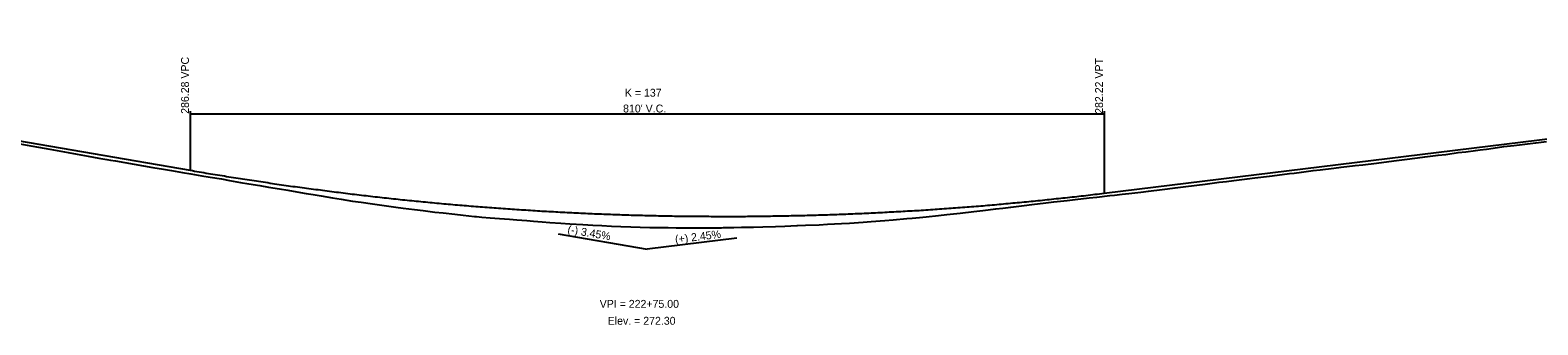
# Model space of a CAD drawing. Extents: x 1876258 to 1926563, y 729739 to 834437.
# Drawn here: x 1900091 to 1901427, y 828757 to 829018 of the extents above; entities that cross this region are included whole.
import ezdxf

# ---------------------------------------------------------------- set-up
doc = ezdxf.new("R2010")
doc.units = 0
for name, color, linetype in [('RD_EX_BldgApp', 7, 'Continuous'), ('RD_EX_H2O_BlueLn', 7, 'Continuous'), ('RD_EX_RailRoad', 7, 'Continuous'), ('RD_HC_Data', 7, 'Continuous'), ('RD_HC_TX_Sta50', 7, 'Continuous'), ('RD_PD_ALT5_CL', 7, 'Continuous')]:
    doc.layers.add(name, color=color, linetype=linetype)

msp = doc.modelspace()

# ---------------------------------------------------------------- linework, layer by layer
at = {"layer": 'RD_EX_BldgApp'}
for points in [[(1900704.1, 828843.2), (1900705.7, 828843.4), (1900711.3, 828843.5), (1900714.9, 828843.6), (1900721.8, 828843.7), (1900732.4, 828843.9), (1900740.7, 828844.2), (1900752, 828844.5), (1900760.1, 828844.7), (1900770.9, 828845.1), (1900771.3, 828845.1), (1900778.6, 828845.4), (1900790.6, 828845.9), (1900798, 828846.3), (1900810.5, 828847), (1900817.6, 828847.4), (1900829.7, 828848.2), (1900836.7, 828848.8), (1900848.8, 828849.6), (1900856.2, 828850.2), (1900868.3, 828851.4), (1900873, 828851.7), (1900879.6, 828852.3), (1900885.5, 828853), (1900896.3, 828854.2), (1900903.6, 828855), (1900915.4, 828856.3), (1900927.7, 828857.7), (1900935.5, 828858.5), (1900947, 828860), (1900953.4, 828860.7), (1900960.5, 828861.6), (1900972.2, 828863), (1900979.1, 828863.8), (1900991.5, 828865.2), (1900998.5, 828866.1), (1901010.3, 828867.4), (1901017.4, 828868.2), (1901029.7, 828869.7), (1901036.5, 828870.4), (1901048.3, 828871.8), (1901052.2, 828872.2), (1901059, 828873), (1901065, 828873.6), (1901075.5, 828874.9), (1901082.5, 828875.8), (1901094.4, 828877.2), (1901106.1, 828878.7), (1901113.1, 828879.5), (1901125.4, 828881), (1901132.7, 828881.9), (1901144.9, 828883.5), (1901151.5, 828884.3), (1901158, 828885.1), (1901169.9, 828886.6), (1901176.6, 828887.4), (1901189.7, 828889.1), (1901196.3, 828889.9), (1901207.4, 828891.2), (1901211.4, 828891.7), (1901218.1, 828892.6), (1901228.2, 828893.9), (1901234.6, 828894.6), (1901246.8, 828896.1), (1901253.1, 828896.9), (1901265.5, 828898.3), (1901272.3, 828899.1), (1901284.4, 828900.6), (1901290.9, 828901.4), (1901302.2, 828902.8), (1901309.2, 828903.6), (1901320.9, 828905.1), (1901327.3, 828906), (1901339, 828907.5), (1901345.9, 828908.3), (1901356.9, 828909.8), (1901363.5, 828910.6), (1901372.1, 828911.7), (1901376.3, 828912.2), (1901382, 828913), (1901391.7, 828914.4), (1901397.2, 828915.1), (1901406.1, 828916.2), (1901411.3, 828916.8), (1901420.5, 828917.9), (1901425.8, 828918.6), (1901435, 828919.7)], [(1900082.1, 828917.5), (1900092.1, 828915.8), (1900098.7, 828914.6), (1900108.7, 828912.8), (1900115.4, 828911.6), (1900125.2, 828909.9), (1900133.1, 828908.4), (1900142.8, 828906.6), (1900152.1, 828905), (1900159.3, 828903.8), (1900162.5, 828903.2), (1900166.9, 828902.4), (1900183.4, 828899.6), (1900200, 828896.7), (1900209.4, 828895.2), (1900216.6, 828894), (1900226.5, 828892.3), (1900233.8, 828891), (1900243.6, 828889.4), (1900250.9, 828888.2), (1900260.8, 828886.5), (1900268.1, 828885.2), (1900277.9, 828883.4), (1900285.3, 828882.3), (1900295, 828880.6), (1900302.5, 828879.3), (1900312.2, 828877.7), (1900319.6, 828876.5), (1900330.9, 828874.5), (1900336, 828873.7), (1900342.1, 828872.6), (1900349.3, 828871.4), (1900359.3, 828869.7), (1900366.9, 828868.5), (1900377.1, 828866.9), (1900384.6, 828865.8), (1900394.8, 828864.4), (1900405.1, 828863), (1900415.3, 828861.5), (1900422, 828860.6), (1900432.1, 828859.3), (1900439.6, 828858.4), (1900449.9, 828857.2), (1900457.3, 828856.4), (1900467.6, 828855.2), (1900475.1, 828854.4), (1900485.2, 828853.3), (1900486.8, 828853.2), (1900491.7, 828852.7), (1900499.1, 828852.1), (1900507.3, 828851.4), (1900516.2, 828850.8), (1900522.8, 828850.2), (1900531.5, 828849.6), (1900537.3, 828849.1), (1900545, 828848.4), (1900551.8, 828847.9), (1900561.6, 828847.2), (1900569.7, 828846.7), (1900581, 828846), (1900589.9, 828845.6), (1900597.9, 828845.1), (1900606.6, 828844.7), (1900614.9, 828844.4), (1900623.8, 828844), (1900631.9, 828843.7), (1900640.6, 828843.6), (1900647.5, 828843.6), (1900656.7, 828843.4), (1900663.9, 828843.3), (1900672.6, 828843.3), (1900680.5, 828843.3), (1900689.5, 828843.3), (1900695.2, 828843.1), (1900704.1, 828843.2)]]:
    msp.add_lwpolyline(points, dxfattribs=at)
at = {"layer": 'RD_EX_H2O_BlueLn'}
for p, q in [((1900233.1, 828946.7), (1900233.1, 828894.2)), ((1901043.1, 828946.7), (1901043.1, 828873.9)), ((1900233.1, 828944.2), (1901043.1, 828944.2))]:
    msp.add_line(p, q, dxfattribs=at)
at = {"layer": 'RD_HC_TX_Sta50'}
for p in [(1900559.2, 828837.9), (1900717.5, 828834)]:
    msp.add_line(p, (1900638.1, 828824.3), dxfattribs=at)
at = {"layer": 'RD_PD_ALT5_CL'}
for p, q in [((1901043.1, 828873.9), (1902223.1, 829018.3)), ((1900043.1, 828927), (1900233.1, 828894.2))]:
    msp.add_line(p, q, dxfattribs=at)
msp.add_spline([(1900233.1, 828894.2), (1900249.3, 828891.4), (1900265.5, 828888.8), (1900281.7, 828886.2), (1900297.9, 828883.8), (1900314.1, 828881.4), (1900330.3, 828879.1), (1900346.5, 828877), (1900362.7, 828874.9), (1900378.9, 828872.9), (1900395.1, 828871), (1900411.3, 828869.2), (1900427.5, 828867.5), (1900443.7, 828865.9), (1900459.9, 828864.4), (1900476.1, 828863), (1900492.3, 828861.7), (1900508.5, 828860.5), (1900524.7, 828859.4), (1900540.9, 828858.3), (1900557.1, 828857.4), (1900573.3, 828856.6), (1900589.5, 828855.8), (1900605.7, 828855.2), (1900621.9, 828854.6), (1900638.1, 828854.2), (1900654.3, 828853.8), (1900670.5, 828853.5), (1900686.7, 828853.4), (1900702.9, 828853.3), (1900719.1, 828853.3), (1900735.3, 828853.5), (1900751.5, 828853.7), (1900767.7, 828854), (1900783.9, 828854.4), (1900800.1, 828854.9), (1900816.3, 828855.5), (1900832.5, 828856.2), (1900848.7, 828857), (1900864.9, 828857.9), (1900881.1, 828858.8), (1900897.3, 828859.9), (1900913.5, 828861.1), (1900929.7, 828862.3), (1900945.9, 828863.7), (1900962.1, 828865.2), (1900978.3, 828866.7), (1900994.5, 828868.4), (1901010.7, 828870.1), (1901026.9, 828871.9), (1901043.1, 828873.9)], degree=3, dxfattribs=at)

# ---------------------------------------------------------------- texts
at = {"layer": 'RD_EX_H2O_BlueLn'}
for s, p in [('K = 137', (1900618.4, 828959.4)), ("810' V.C.", (1900616.8, 828945.4))]:
    msp.add_text(s, height=7, dxfattribs=at).set_placement(p)
at = {"layer": 'RD_EX_RailRoad'}
for s, p in [('286.28 VPC', (1900232.1, 828944.2)), ('282.22 VPT', (1901042.1, 828944.2))]:
    msp.add_text(s, height=7, rotation=90, dxfattribs=at).set_placement(p)
at = {"layer": 'RD_HC_Data'}
for s, p in [('VPI = 222+75.00', (1900596.1, 828772.3)), ('Elev. = 272.30', (1900603.2, 828757.3))]:
    msp.add_text(s, height=7, dxfattribs=at).set_placement(p)
at = {"layer": 'RD_HC_TX_Sta50'}
for s, rotation, p in [('(-) 3.45%', 350.2089, (1900567.2, 828838.6)), ('(+) 2.45%', 6.9798, (1900663.3, 828829.4))]:
    msp.add_text(s, height=7, rotation=rotation, dxfattribs=at).set_placement(p)

doc.saveas('drawing.dxf')
